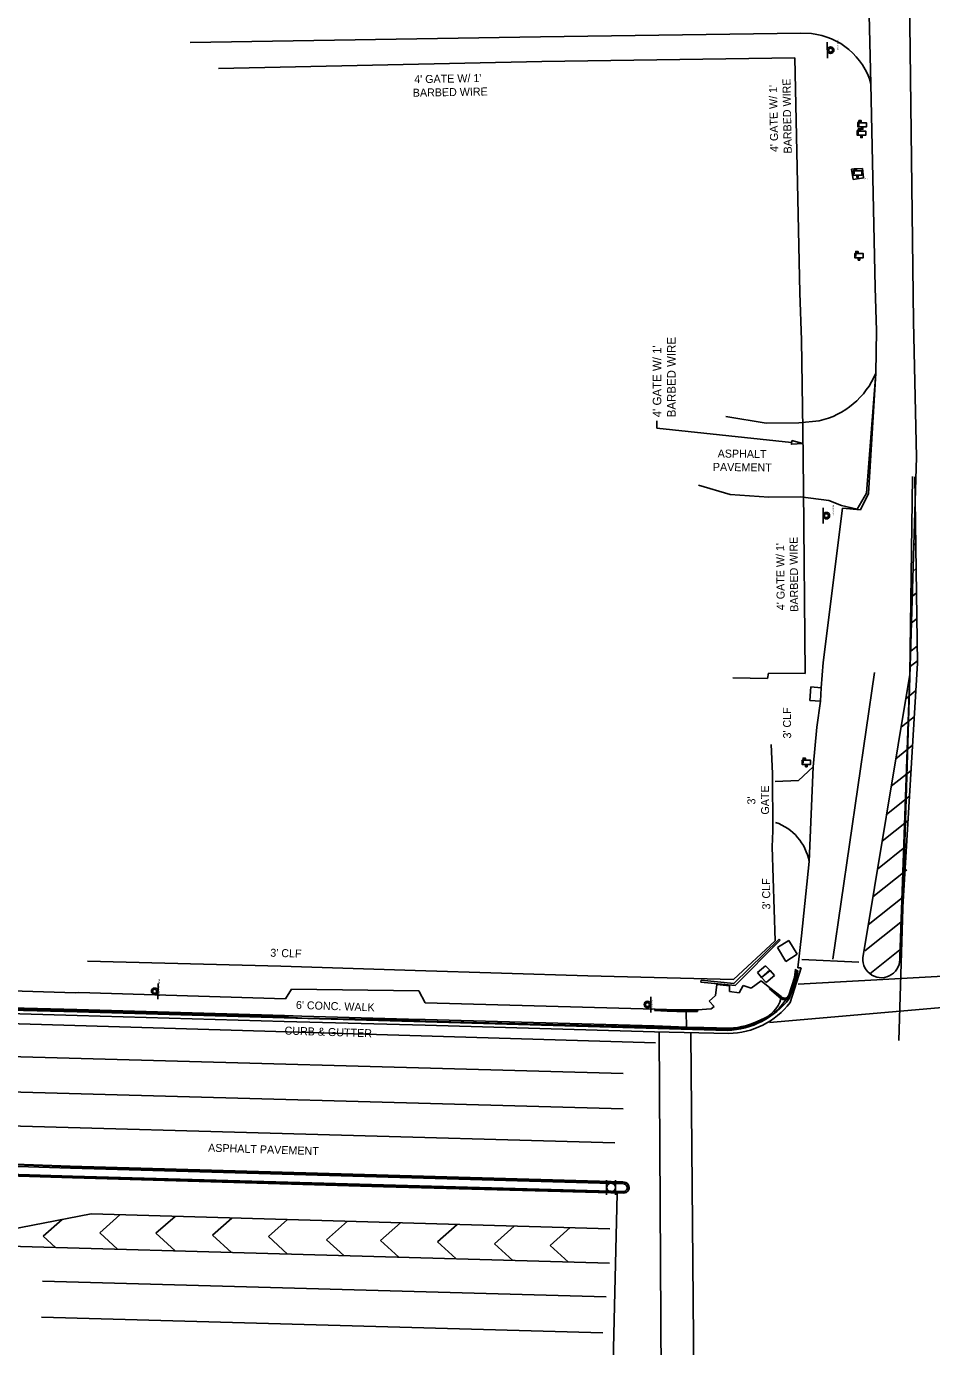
# Model space of a CAD drawing. Extents: x 925226 to 926411, y 852913 to 858733.
# Drawn here: x 925524.4 to 925841.1, y 853526.6 to 853988.5 of the extents above; entities that cross this region are included whole.
import ezdxf

# ---------------------------------------------------------------- set-up
doc = ezdxf.new("R2010")
doc.units = 0
for name, color, linetype in [('CGep_ep', 7, 'Continuous'), ('CGFace_ep', 7, 'Continuous'), ('CLConst_dp', 7, 'Continuous'), ('ConcSlabs_ep', 7, 'Continuous'), ('CurbRamp_ep', 7, 'Continuous'), ('DelineatorPost_ep', 7, 'Continuous'), ('Driveway_ep', 7, 'Continuous'), ('EndTreat_ep', 7, 'Continuous'), ('Fence_ep', 7, 'Continuous'), ('Gates_ep', 7, 'Continuous'), ('InletCurb_ep', 7, 'Continuous'), ('LaneLine_ep', 7, 'Continuous'), ('ManholeSW_ep', 7, 'Continuous'), ('PavtAsphalt_ep', 7, 'Continuous'), ('PavtCrown_ep', 7, 'Continuous'), ('PavtMisc_ep', 7, 'Continuous'), ('SidewalkBack_ep', 7, 'Continuous'), ('TextLabel', 7, 'Continuous'), ('WallRetainEarth_ep', 7, 'Continuous'), ('XSPt_ep', 7, 'Continuous')]:
    doc.layers.add(name, color=color, linetype=linetype)

# ---------------------------------------------------------------- blocks, each defined once
blk = doc.blocks.new('SSS')
at = {"layer": 'ManholeSW_ep'}
blk.add_line((-2.77, 1.15), (2.77, 1.15), dxfattribs=at)
for radius in [1.15, 0.692]:
    blk.add_circle((0, 0), radius, dxfattribs=at)
blk = doc.blocks.new('MBX')
at = {"layer": 'InletCurb_ep'}
for points in [[(-1.5, 1.42), (-1.5, 1.45), (1.5, 1.45), (1.5, 0), (-1.5, 0), (-1.5, 1.42), (-1.53, 1.55), (-1.59, 1.55)], [(-1.15, 0.38), (-1.15, 2.22), (-0.33, 2.22), (-0.33, 1.7), (-1.15, 1.7)], [(0.26, 0), (0.26, -0.82), (-0.26, -0.82), (-0.26, 0)]]:
    blk.add_lwpolyline(points, dxfattribs=at)
blk = doc.blocks.new('DLP')
at = {"layer": 'DelineatorPost_ep'}
for p, q in [((-1.54, -2.57), (-1.54, 2.57)), ((1.54, -2.57), (1.54, 2.57))]:
    blk.add_line(p, q, dxfattribs=at)
blk.add_circle((0, 0), 1.54, dxfattribs=at)

msp = doc.modelspace()

# ---------------------------------------------------------------- linework, layer by layer
at = {"layer": 'CGep_ep'}
for p, q in [((925793.78, 853655.13), (925794.32, 853658.06)), ((925791.25, 853648.37), (925793.78, 853655.13)), ((925784.48, 853652.18), (925784.3, 853651.78)), ((925784.3, 853651.78), (925788.37, 853648.43)), ((925453.7, 853646.2), (925542.22, 853643.68)), ((925542.22, 853643.68), (925614.6, 853641.62)), ((925614.6, 853641.62), (925664.03, 853640.22)), ((925664.03, 853640.22), (925769.65, 853637.2))]:
    msp.add_line(p, q, dxfattribs=at)
for centre, major_axis, ratio, start_param, end_param in [((925768.33, 853666.21), (27.29, -9.96), 0.999913, 5.107569, 5.971501), ((925789.85, 853650.12), (-0.71, 2.13), 0.996396, 2.102376, 3.499746)]:
    msp.add_ellipse(centre, major_axis=major_axis, ratio=ratio, start_param=start_param, end_param=end_param, dxfattribs=at)
at = {"layer": 'CGFace_ep'}
for p, q in [((925793.9, 853658.19), (925793.45, 853655.2)), ((925793.45, 853655.2), (925791.34, 853649.28)), ((925788.45, 853648.58), (925784.3, 853651.78)), ((925519.11, 853644.64), (925542.21, 853644.03)), ((925542.21, 853644.03), (925614.63, 853642.02)), ((925744.17, 853644.17), (925752.4, 853644.04)), ((925752.4, 853644.04), (925759.19, 853643.87)), ((925614.63, 853642.02), (925620.79, 853641.55)), ((925620.79, 853641.55), (925658.09, 853640.76)), ((925658.09, 853640.76), (925664.06, 853640.46)), ((925664.06, 853640.46), (925744.21, 853638.33)), ((925744.21, 853638.33), (925749.85, 853638.11)), ((925749.85, 853638.11), (925755.29, 853638.02)), ((925755.29, 853638.02), (925761.38, 853637.78)), ((925761.38, 853637.78), (925770.08, 853637.74)), ((925488.99, 853591.27), (925539.79, 853589.52)), ((925539.79, 853589.52), (925650.93, 853586.36)), ((925540.53, 853585.78), (925489.02, 853587.49)), ((925649.32, 853582.78), (925540.53, 853585.78)), ((925650.93, 853586.36), (925733.2, 853584.03)), ((925733.17, 853580.4), (925649.32, 853582.78))]:
    msp.add_line(p, q, dxfattribs=at)
for centre, major_axis, ratio, start_param, end_param in [((925789.65, 853649.91), (1.09, -1.43), 0.999241, 4.898091, 6.843143), ((925772.72, 853658.99), (13.17, 15.98), 0.988966, 4.125198, 4.826209), ((925769.65, 853663.78), (-26.18, -1.71), 0.992699, 1.522424, 1.853583), ((925733.32, 853582.21), (1.81, 0.2), 0.999267, 4.520263, 7.812169)]:
    msp.add_ellipse(centre, major_axis=major_axis, ratio=ratio, start_param=start_param, end_param=end_param, dxfattribs=at)
at = {"layer": 'ConcSlabs_ep'}
for p, q in [((925816.85, 853938.79), (925813.08, 853938.47)), ((925813.08, 853938.47), (925813.57, 853934.91)), ((925813.57, 853934.91), (925817.24, 853935.46)), ((925817.24, 853935.46), (925816.85, 853938.79)), ((925798.79, 853757.42), (925798.51, 853752.68)), ((925802.45, 853757.08), (925798.79, 853757.42)), ((925802.17, 853752.36), (925802.45, 853757.08)), ((925798.51, 853752.68), (925802.17, 853752.36)), ((925787.14, 853666.25), (925791.11, 853668.63)), ((925791.11, 853668.63), (925794.04, 853663.9)), ((925790.06, 853661.38), (925787.14, 853666.25)), ((925794.04, 853663.9), (925790.06, 853661.38)), ((925782.99, 853659.85), (925780.1, 853657.45)), ((925780.1, 853657.45), (925781.55, 853655.72)), ((925784.42, 853658.28), (925781.55, 853655.72)), ((925781.55, 853655.71), (925784.54, 853658.23)), ((925784.42, 853658.28), (925782.99, 853659.85)), ((925784.54, 853658.23), (925784.42, 853658.28)), ((925786.15, 853656.49), (925784.54, 853658.23)), ((925781.55, 853655.72), (925781.55, 853655.71)), ((925781.55, 853655.71), (925783.15, 853653.97)), ((925783.15, 853653.97), (925786.15, 853656.49))]:
    msp.add_line(p, q, dxfattribs=at)
at = {"layer": 'CurbRamp_ep'}
msp.add_line((925755.29, 853638.42), (925755.23, 853643.69), dxfattribs=at)
at = {"layer": 'Driveway_ep'}
for p, q in [((925818.28, 853825.18), (925821.53, 853867.16)), ((925783.23, 853849.68), (925769.04, 853851.99)), ((925794.6, 853849.81), (925783.23, 853849.68)), ((925801.76, 853850.48), (925794.6, 853849.81)), ((925770.6, 853824.71), (925759.5, 853827.98)), ((925784.12, 853823.77), (925770.6, 853824.71)), ((925795.25, 853823.84), (925784.12, 853823.77)), ((925805.06, 853822.66), (925795.25, 853823.84)), ((925815.04, 853819.58), (925818.28, 853825.18)), ((925809.59, 853820.91), (925805.06, 853822.66)), ((925815.04, 853819.58), (925809.59, 853820.91))]:
    msp.add_line(p, q, dxfattribs=at)
msp.add_ellipse((925795.52, 853877.93), major_axis=(23.35, 15.73), ratio=0.999711, start_param=4.343329, end_param=5.29757, dxfattribs=at)
at = {"layer": 'EndTreat_ep'}
for p, q in [((925833.42, 853761.73), (925834.42, 853831.04)), ((925836.18, 853765.71), (925835.22, 853830.85)), ((925835.07, 853813.69), (925835.47, 853814.01)), ((925834.87, 853806.99), (925835.56, 853807.55)), ((925834.59, 853797.89), (925835.69, 853798.77)), ((925834.33, 853789.13), (925835.82, 853790.32)), ((925834.05, 853779.79), (925835.95, 853781.31)), ((925833.75, 853769.91), (925836.09, 853771.78)), ((925829.9, 853662.98), (925836.18, 853765.71)), ((925833.59, 853764.5), (925836.16, 853766.55)), ((925806.45, 853662.2), (925821.12, 853762.49)), ((925817, 853662.66), (925833.42, 853761.73)), ((925833.42, 853761.73), (925829.9, 853662.98)), ((925832.01, 853753.26), (925835.59, 853756.12)), ((925830.37, 853743.33), (925835.04, 853747.06)), ((925828.54, 853732.28), (925834.42, 853736.98)), ((925826.94, 853722.66), (925833.89, 853728.21)), ((925825.29, 853712.71), (925833.33, 853719.13)), ((925823.76, 853703.44), (925832.82, 853710.68)), ((925822.14, 853693.66), (925832.27, 853701.75)), ((925820.53, 853683.96), (925832.41, 853693.45)), ((925818.91, 853674.18), (925831.32, 853684.09)), ((925817.72, 853665.03), (925830.34, 853675.11)), ((925815.65, 853661.12), (925795.71, 853662.04)), ((925819.5, 853657.05), (925829.99, 853665.43)), ((925855.72, 853656.82), (925794.38, 853653.47)), ((925238.1, 853647.9), (925744.48, 853632.89)), ((925784.3, 853639.95), (925875.93, 853647.95)), ((925746.46, 853504.49), (925745.81, 853636.38)), ((925756.83, 853636.13), (925757.98, 853503.54)), ((925729.28, 853504.82), (925731.08, 853580.21)), ((925547.06, 853573.02), (925492.16, 853562.52)), ((925530.33, 853565.2), (925536.97, 853571.09)), ((925728.52, 853567.83), (925547.06, 853573.02)), ((925550.04, 853566.44), (925557.13, 853572.73)), ((925569.74, 853566.28), (925576.39, 853572.18)), ((925589.53, 853565.66), (925596.24, 853571.61)), ((925609.08, 853565.11), (925615.78, 853571.05)), ((925629.39, 853563.93), (925636.75, 853570.45)), ((925648.28, 853563.73), (925655.27, 853569.93)), ((925534.58, 853561.31), (925530.33, 853565.2)), ((925556.33, 853560.69), (925550.04, 853566.44)), ((925576.49, 853560.11), (925569.74, 853566.28)), ((925596.2, 853559.55), (925589.53, 853565.66)), ((925615.77, 853558.99), (925609.08, 853565.11)), ((925668.25, 853563.29), (925675.09, 853569.36)), ((925688.13, 853562.62), (925695.09, 853568.79)), ((925707.64, 853562.02), (925714.64, 853568.23)), ((925492.16, 853562.52), (925728.38, 853555.78)), ((925635.4, 853558.44), (925629.39, 853563.93)), ((925654.66, 853557.9), (925648.28, 853563.73)), ((925674.62, 853557.46), (925668.25, 853563.29)), ((925694.51, 853556.79), (925688.13, 853562.62)), ((925714.02, 853556.19), (925707.64, 853562.02)), ((925727.18, 853543.98), (925530, 853549.48)), ((925726.07, 853531.41), (925529.64, 853536.89))]:
    msp.add_line(p, q, dxfattribs=at)
msp.add_arc((925823.47, 853662.17), 6.49, 175.7197, 7.1858, dxfattribs=at)
at = {"layer": 'Fence_ep'}
for p, q in [((925591.62, 853973.69), (925704.73, 853976.14)), ((925704.73, 853976.14), (925793.16, 853977.47)), ((925793.16, 853977.47), (925794.91, 853895.24)), ((925794.91, 853895.24), (925795.49, 853878.71)), ((925795.97, 853847.37), (925795.49, 853878.71)), ((925796.87, 853762.05), (925796.3, 853826.69)), ((925783.69, 853760.39), (925771.58, 853760.57)), ((925783.69, 853760.39), (925783.97, 853762.2)), ((925783.97, 853762.2), (925796.87, 853762.05)), ((925785.45, 853727.1), (925784.96, 853737.21)), ((925785.32, 853701.43), (925785.49, 853707)), ((925786.34, 853668.6), (925785.32, 853701.43)), ((925771.78, 853655), (925786.34, 853668.6)), ((925613.4, 853659.69), (925545.74, 853661.42)), ((925660.45, 853658.25), (925613.4, 853659.69)), ((925720.78, 853656.33), (925660.45, 853658.25)), ((925720.78, 853656.33), (925771.78, 853655))]:
    msp.add_line(p, q, dxfattribs=at)
at = {"layer": 'Gates_ep'}
for p, q in [((925795.97, 853847.37), (925796.3, 853826.69)), ((925785.49, 853707), (925785.45, 853727.1))]:
    msp.add_line(p, q, dxfattribs=at)
at = {"layer": 'LaneLine_ep'}
for p, q in [((925733.11, 853622.14), (925237.81, 853635.95)), ((925733.11, 853609.75), (925237.81, 853623.57)), ((925730.19, 853597.93), (925234.89, 853611.75))]:
    msp.add_line(p, q, dxfattribs=at)
at = {"layer": 'PavtAsphalt_ep'}
for p, q in [((925819.85, 853968.35), (925819.15, 853997.45)), ((925821.3, 853897.12), (925819.85, 853968.35)), ((925821.3, 853897.12), (925821.75, 853882.01)), ((925821.75, 853882.01), (925821.53, 853867.16)), ((925821.53, 853867.16), (925818.94, 853825.06)), ((925818.94, 853825.06), (925816.21, 853819.31)), ((925809.9, 853819.93), (925803.17, 853765.9)), ((925816.21, 853819.31), (925809.9, 853819.93)), ((925802.45, 853757.08), (925803.17, 853765.9)), ((925800.93, 853743.33), (925802.17, 853752.36)), ((925799.6, 853729.42), (925800.93, 853743.33)), ((925794.49, 853724.63), (925799.6, 853729.42)), ((925799.6, 853729.42), (925798.23, 853696.33)), ((925786.38, 853724.34), (925794.49, 853724.63)), ((925795.58, 853670.28), (925798.23, 853696.33)), ((925795.58, 853670.28), (925794.32, 853659.08)), ((925791.56, 853646.95), (925795.46, 853659.15)), ((925794.32, 853659.08), (925795.46, 853659.15)), ((925453.68, 853645.07), (925542.21, 853642.47)), ((925542.21, 853642.47), (925614.59, 853640.39)), ((925614.59, 853640.39), (925663.92, 853639.02)), ((925663.92, 853639.02), (925744.17, 853636.77)), ((925744.17, 853636.77), (925770.02, 853636.15)), ((925489.04, 853591.53), (925539.69, 853589.71)), ((925539.69, 853589.71), (925650.95, 853586.65)), ((925540.54, 853585.67), (925489.1, 853587.27)), ((925649.32, 853582.55), (925540.54, 853585.67)), ((925650.95, 853586.65), (925733.09, 853584.21)), ((925733.26, 853580.3), (925649.32, 853582.55))]:
    msp.add_line(p, q, dxfattribs=at)
for centre, major_axis, ratio, start_param, end_param in [((925780.49, 853692.88), (-6.93, -16.77), 0.994875, 2.152223, 3.196169), ((925769.53, 853664.02), (25.61, -11.01), 0.999903, 5.136073, 6.030051), ((925733.29, 853582.26), (1.87, 0.6), 0.998841, 4.386141, 7.647165)]:
    msp.add_ellipse(centre, major_axis=major_axis, ratio=ratio, start_param=start_param, end_param=end_param, dxfattribs=at)
at = {"layer": 'PavtCrown_ep'}
for p, q in [((925833.25, 854002.14), (925834.7, 853885.26)), ((925834.7, 853885.26), (925835.8, 853837.78)), ((925835.8, 853837.78), (925829.64, 853633.69))]:
    msp.add_line(p, q, dxfattribs=at)
at = {"layer": 'PavtMisc_ep'}
for p, q in [((925704.25, 853984.83), (925795.36, 853986.11)), ((925795.36, 853986.11), (925799.05, 853985.94)), ((925581.7, 853982.8), (925704.25, 853984.83))]:
    msp.add_line(p, q, dxfattribs=at)
msp.add_ellipse((925796.48, 853961.78), major_axis=(-0.35, 24.3), ratio=0.999055, start_param=4.971951, end_param=6.162689, dxfattribs=at)
at = {"layer": 'SidewalkBack_ep'}
for p, q in [((925765.47, 853649.48), (925765.91, 853653.26)), ((925765.91, 853653.26), (925770.4, 853652.81)), ((925770.4, 853652.81), (925770.31, 853650.9)), ((925773.77, 853650.4), (925775.17, 853652.89)), ((925775.17, 853652.89), (925777.94, 853651.96)), ((925777.94, 853651.96), (925781.38, 853654.56)), ((925781.38, 853654.56), (925784.48, 853652.18)), ((925519.18, 853651.1), (925541.54, 853650.42)), ((925541.54, 853650.42), (925542.75, 853650.44)), ((925542.75, 853650.44), (925615.01, 853648.31)), ((925615.01, 853648.31), (925617.15, 853651.7)), ((925617.15, 853651.7), (925661.72, 853651.1)), ((925661.72, 853651.1), (925663.94, 853646.87)), ((925763.25, 853647.42), (925765.47, 853649.48)), ((925770.31, 853650.9), (925773.77, 853650.4)), ((925663.94, 853646.87), (925744.31, 853644.62)), ((925744.31, 853644.62), (925744.17, 853644.17)), ((925744.17, 853644.17), (925748.6, 853643.93)), ((925748.6, 853643.93), (925755.23, 853643.69)), ((925755.23, 853643.69), (925759.19, 853643.87)), ((925759.19, 853643.87), (925759.31, 853644.43)), ((925759.31, 853644.43), (925763.84, 853644.78)), ((925764.96, 853645.62), (925763.25, 853647.42)), ((925763.84, 853644.78), (925763.99, 853644.83)), ((925763.99, 853644.83), (925764.96, 853645.62))]:
    msp.add_line(p, q, dxfattribs=at)
at = {"layer": 'TextLabel'}
for points in [[(925744.92, 853847.9), (925744.92, 853850.44)], [(925792.07, 853842.93), (925744.92, 853847.9)]]:
    msp.add_lwpolyline(points, dxfattribs=at)
msp.add_lwpolyline([(925792.14, 853843.59), (925796.05, 853842.51), (925792, 853842.26)], close=True, dxfattribs=at)
at = {"layer": 'WallRetainEarth_ep'}
for p, q in [((925787.76, 853669.12), (925771.85, 853653.65)), ((925772.29, 853652.99), (925788.09, 853668.8)), ((925788.09, 853668.8), (925787.76, 853669.12)), ((925760.4, 853654.77), (925760.35, 853654.09)), ((925760.35, 853654.09), (925772.29, 853652.99)), ((925771.85, 853653.65), (925760.4, 853654.77))]:
    msp.add_line(p, q, dxfattribs=at)
at = {"layer": 'XSPt_ep'}
for p, q in [((925793.41, 853658.7), (925793.07, 853655.8)), ((925793.41, 853658.7), (925793.9, 853658.19)), ((925793.9, 853658.19), (925794.32, 853658.06)), ((925793.07, 853655.8), (925791.07, 853649.59)), ((925788.43, 853649.07), (925784.48, 853652.18)), ((925519.1, 853645.11), (925542.08, 853644.55)), ((925542.08, 853644.55), (925614.66, 853642.49)), ((925744.31, 853644.62), (925752.39, 853644.48)), ((925752.39, 853644.48), (925759.31, 853644.43)), ((925614.66, 853642.49), (925620.8, 853642.17)), ((925620.8, 853642.17), (925658.09, 853641.17)), ((925658.09, 853641.17), (925663.93, 853641)), ((925663.93, 853641), (925744.06, 853638.8)), ((925744.06, 853638.8), (925749.79, 853638.6)), ((925749.79, 853638.6), (925755.29, 853638.42)), ((925755.29, 853638.42), (925761.39, 853638.3)), ((925761.39, 853638.3), (925770.28, 853638.01)), ((925489.04, 853590.74), (925539.87, 853589.05)), ((925539.87, 853589.05), (925650.93, 853585.94)), ((925540.53, 853586.26), (925488.89, 853587.93)), ((925649.33, 853583.24), (925540.53, 853586.26)), ((925650.93, 853585.94), (925733.33, 853583.51)), ((925733.16, 853580.89), (925649.33, 853583.24))]:
    msp.add_line(p, q, dxfattribs=at)
for centre, major_axis, ratio, start_param, end_param in [((925778, 853651.24), (5.67, 9.3), 0.985349, 4.008935, 4.991784), ((925789.62, 853649.97), (-0.6, -1.37), 0.998698, 5.766555, 8.011408), ((925769.3, 853663.52), (-25.51, -4.88), 0.98266, 1.422724, 1.866254), ((925733.27, 853582.2), (1.27, 0.33), 0.998072, 4.369893, 7.548071)]:
    msp.add_ellipse(centre, major_axis=major_axis, ratio=ratio, start_param=start_param, end_param=end_param, dxfattribs=at)

# ---------------------------------------------------------------- block references
at = {"layer": 'DelineatorPost_ep'}
msp.add_blockref('DLP', (925728.93, 853582.28), dxfattribs=at)
at = {"layer": 'InletCurb_ep'}
for p in [(925816.78, 853953.32), (925816.54, 853950.39), (925815.15, 853936.46), (925815.65, 853907.55), (925797.22, 853730.29)]:
    msp.add_blockref('MBX', p, dxfattribs=at)
at = {"layer": 'ManholeSW_ep'}
for p, rotation in [((925805.74, 853980.15), 90.5368174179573), ((925804.24, 853817.31), 89.68823096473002), ((925569.28, 853650.92), -91.44771840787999), ((925741.66, 853646.26), -90.00000000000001)]:
    msp.add_blockref('SSS', p, dxfattribs=dict(at, rotation=rotation))

# ---------------------------------------------------------------- texts
at = {"layer": 'CLConst_dp'}
for s, rotation, p in [('STOP SIGN', 90.5368, (925808.44, 853980.16)), ('STOP SIGN', 89.6882, (925806.93, 853817.3)), ('INTERSTATE SIGN', 88.5523, (925570.97, 853649.07)), ('BIKE LANE', 90, (925743.32, 853644.34))]:
    msp.add_text(s, height=0.5, rotation=rotation, dxfattribs=at).set_placement(p)
msp.add_text('USPS', height=0.5, dxfattribs=at).set_placement((925816.69, 853934.94))
at = {"layer": 'TextLabel'}
for s, height, rotation, p in [("4' GATE W/ 1' ", 2.8, 1.0261, (925660.1, 853968.58)), ('BARBED WIRE', 2.8, 1.0261, (925659.59, 853963.85)), ("4' GATE W/ 1' ", 2.8, 91.0261, (925787.41, 853944.54)), ('BARBED WIRE', 2.8, 91.0261, (925792.14, 853944.04)), ('BARBED WIRE', 3, 90, (925751.54, 853851.73)), ("4' GATE W/ 1'", 3, 90, (925746.51, 853851.74)), ('ASPHALT ', 2.8, 359.3465, (925766.21, 853837.66)), ('PAVEMENT', 2.8, 359.3465, (925764.53, 853832.97)), ('BARBED WIRE', 2.8, 90.5061, (925794.39, 853783.71)), ("4' GATE W/ 1' ", 2.8, 90.5061, (925789.67, 853784.25)), ("3' CLF", 2.8, 90.5061, (925791.93, 853739.36)), ('GATE', 2.8, 90.5061, (925784.21, 853712.75)), ("3' ", 2.8, 90.5061, (925779.42, 853716.27)), ("3' CLF", 2.8, 90.5061, (925784.64, 853679.54)), ("3' CLF", 2.8, 358.1724, (925609.69, 853663.03)), ("6' CONC. WALK", 2.8, 358.1724, (925618.65, 853644.77)), ('CURB & GUTTER', 2.8, 358.1724, (925614.68, 853635.79)), ('ASPHALT PAVEMENT', 2.8, 358.1724, (925587.95, 853594.84))]:
    msp.add_text(s, height=height, rotation=rotation, dxfattribs=at).set_placement(p)

doc.saveas('drawing.dxf')
